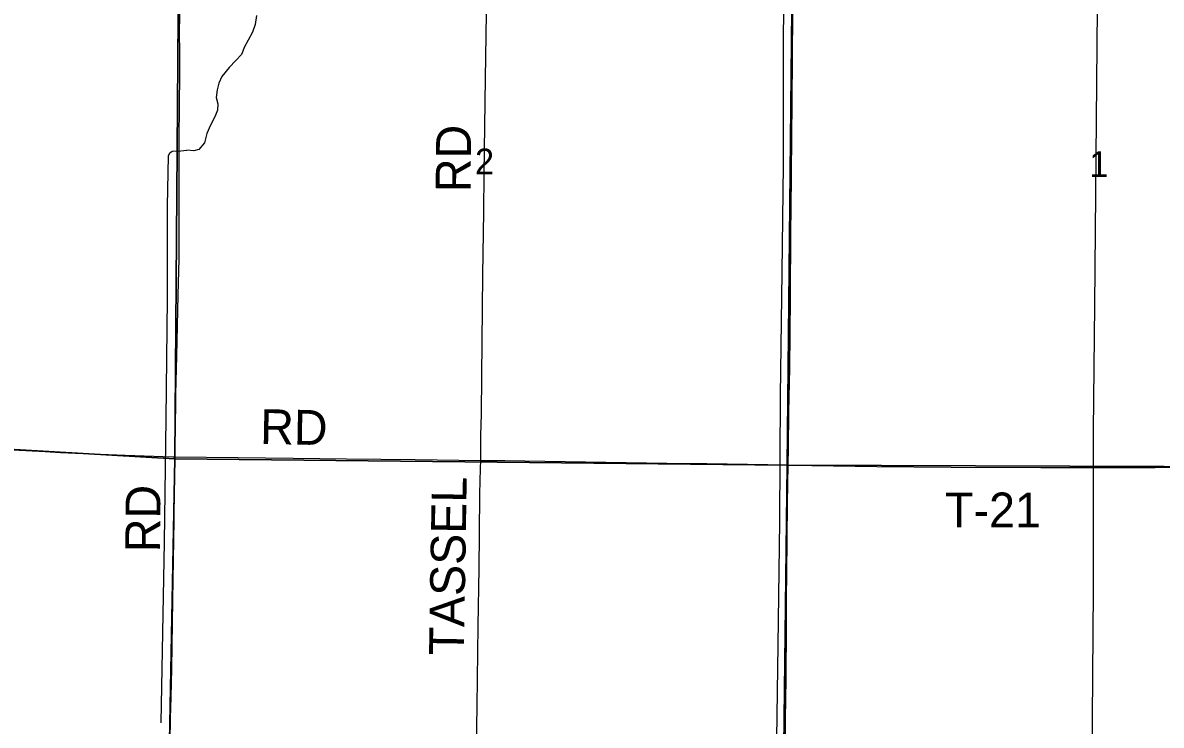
# Model space of a CAD drawing. Extents: x 1443599 to 1910620, y 1028088 to 1361369.
# Drawn here: x 1608527 to 1618321, y 1212815 to 1218862 of the extents above; entities that cross this region are included whole.
import ezdxf

# ---------------------------------------------------------------- set-up
doc = ezdxf.new("R2010")
doc.units = 0
for name, color, linetype in [('GM_X_Minor_River', 7, 'Continuous'), ('GM_X_Section', 7, 'Continuous'), ('GM_X_Section_Text', 7, 'Continuous'), ('GM_X_State_Route', 7, 'Continuous'), ('GM_X_Township_Road', 7, 'Continuous'), ('GM_X_Township_Road_Text', 7, 'Continuous')]:
    doc.layers.add(name, color=color, linetype=linetype)

msp = doc.modelspace()

# ---------------------------------------------------------------- linework, layer by layer
at = {"layer": 'GM_X_Minor_River'}
for points in [[(1617853.3, 1226327.9), (1617840.1, 1225049.4), (1617825.5, 1224051.8), (1617810.7, 1222799.8), (1617798, 1221193.2), (1617782.7, 1220157.6), (1617771.2, 1218983.8), (1617758, 1217707.9), (1617748.7, 1216428), (1617736.7, 1215352.4), (1617735.8, 1213978.3), (1617725.2, 1212506.2), (1617715, 1211422.7), (1617702.4, 1210197), (1617703.6, 1209429.7), (1617680.8, 1208428.5), (1617671.9, 1207420.9), (1617660.9, 1206527.6), (1617638.1, 1205167.5)], [(1615135.5, 1225234.5), (1615129.9, 1224405.5), (1615117.6, 1223546.2), (1615116.2, 1222376.2), (1615099.6, 1221134.4), (1615094.5, 1220467.4), (1615092.3, 1219854.4), (1615068.3, 1218777), (1615067.4, 1217637.2), (1615056, 1216713.9), (1615044.3, 1215650.5), (1615036.1, 1214564.9), (1615022.5, 1213507.5), (1615006.2, 1212293.8)], [(1610539, 1218924.3), (1610525.7, 1218846.4), (1610504.5, 1218780.7), (1610465.3, 1218711.3), (1610434.3, 1218653.7), (1610407.2, 1218590.1), (1610360.3, 1218536.9), (1610301.2, 1218475.8), (1610239.9, 1218400.8), (1610212.8, 1218341.2), (1610199.9, 1218285.3), (1610190.8, 1218219.4), (1610203.9, 1218163), (1610201, 1218111), (1610178, 1218053.3), (1610140.7, 1217979.8), (1610111.5, 1217910.2), (1610090.2, 1217828.5), (1610041.9, 1217772.2), (1609999.3, 1217760), (1609938.9, 1217765.1)], [(1609716.5, 1212835.8), (1609746.5, 1214392.3), (1609760.2, 1215456.1), (1609771.4, 1216485.8), (1609772.7, 1217283.2), (1609779.9, 1217715.9), (1609792.4, 1217743.7), (1609812.6, 1217757.3), (1609886.8, 1217760), (1609938.9, 1217765.1)]]:
    msp.add_lwpolyline(points, dxfattribs=at)
at = {"layer": 'GM_X_Section'}
for points in [[(1604565.2, 1220497.6), (1609830.1, 1220437.4), (1609876.1, 1220436.7), (1609835, 1215109.4), (1607170.3, 1215264), (1604507.5, 1215126.5)], [(1615157.1, 1220376.3), (1615104, 1215053), (1609835, 1215109.4), (1609876.1, 1220436.7)], [(1620446.9, 1220363.7), (1620417.2, 1215002), (1619967.5, 1215036.6), (1615104, 1215053), (1615157.1, 1220376.3)], [(1604507.5, 1215126.5), (1607170.3, 1215264), (1609835, 1215109.4), (1609736, 1209792.9), (1604408.8, 1209830.1)], [(1609835, 1215109.4), (1615104, 1215053), (1615038.9, 1209730), (1609736, 1209792.9)], [(1615104, 1215053), (1619967.5, 1215036.6), (1620417.2, 1215002), (1620382.4, 1209704.6), (1615038.9, 1209730)]]:
    msp.add_lwpolyline(points, close=True, dxfattribs=at)
at = {"layer": 'GM_X_State_Route'}
msp.add_lwpolyline([(1615085.8, 1212392.6), (1615089.7, 1212868.6), (1615093.7, 1213213.2), (1615097.7, 1213672.7), (1615098.4, 1213919), (1615101.7, 1214115.8), (1615107.4, 1214723.1), (1615112.1, 1215055.7), (1615114.1, 1215199), (1615118.6, 1215510.9), (1615125.8, 1215888.3), (1615131.6, 1216495.5), (1615135.6, 1217070), (1615138.4, 1217250.5), (1615145.6, 1218186), (1615151.6, 1218941), (1615152.7, 1219006.6)], dxfattribs=at)
at = {"layer": 'GM_X_Township_Road'}
for points in [[(1612468.4, 1215095.4), (1612468.5, 1215132.1), (1612469.1, 1215312.7), (1612473, 1215493.2), (1612475.9, 1215821.5), (1612486.2, 1216691.6), (1612493.2, 1217233.3), (1612496.8, 1217561.7), (1612507.9, 1218382.5), (1612516, 1218940.6), (1612518, 1219058.9)], [(1609835, 1215124.2), (1609835.9, 1215189.4), (1609841.3, 1215402.7), (1609844.6, 1215583.1), (1609844.4, 1215665.2), (1609853.2, 1215993.2), (1609856.3, 1216124.5), (1609864.1, 1216518.2), (1609871.7, 1216829.9), (1609872.2, 1216895.5), (1609871.2, 1216961.1), (1609873.3, 1217043.1), (1609872.6, 1217108.8), (1609873, 1217240.1), (1609872.5, 1217519), (1609873.1, 1217617.4), (1609872.4, 1217715.9), (1609871.3, 1217781.5), (1609872.1, 1217847.2), (1609874.8, 1218158.9), (1609876.9, 1218407.3), (1609878.6, 1218618.4), (1609874.2, 1218765.9), (1609877.8, 1218937.3)], [(1607200.5, 1215257.7), (1607261.2, 1215256), (1607457.9, 1215244.8), (1607801.9, 1215222.2), (1608162.4, 1215201.9), (1608440.9, 1215185.8), (1608719.5, 1215171.1), (1608850.6, 1215164.1), (1608981.6, 1215158.3), (1609408, 1215141.1), (1609817.9, 1215124.4), (1609835, 1215124.2)], [(1609749.8, 1209795.4), (1609753.4, 1210037.6), (1609758.8, 1210267.3), (1609762.8, 1210513.4), (1609766.1, 1210693.9), (1609770.5, 1211022), (1609775.1, 1211333.8), (1609776.9, 1211448.6), (1609781.4, 1211678.3), (1609789.8, 1212383.8), (1609791.7, 1212482.3), (1609794.8, 1212679.1), (1609799.1, 1212876), (1609803.2, 1213056.4), (1609808, 1213302.5), (1609817.6, 1213893.2), (1609828, 1214582.3), (1609835, 1215124.2)], [(1609835, 1215124.2), (1610375.8, 1215118.6), (1610851.9, 1215113), (1611311.3, 1215107.2), (1611902.2, 1215102.2), (1612468.4, 1215095.4)], [(1612437.1, 1209776.3), (1612436.5, 1209827.4), (1612435.1, 1209975.3), (1612440, 1210583.3), (1612445.7, 1211224.2), (1612451.8, 1211733.6), (1612456.3, 1211897.9), (1612455.5, 1212045.7), (1612453.9, 1212259.4), (1612450.7, 1212341.4), (1612441.3, 1212489), (1612435.9, 1212636.8), (1612433.7, 1212801.2), (1612435, 1212981.9), (1612440.6, 1213442), (1612444.3, 1213672), (1612452.4, 1214165), (1612456.2, 1214460.8), (1612460.2, 1214805.8), (1612466, 1215025.5), (1612468.4, 1215095.4)], [(1612468.4, 1215095.4), (1612673.6, 1215093), (1613018.2, 1215087.9), (1613543.5, 1215080.7), (1614068.6, 1215071.9), (1614413.3, 1215067.4), (1615112.1, 1215055.7)], [(1615112.1, 1215055.7), (1615250.2, 1215053.4), (1615315.9, 1215051.3), (1615873.8, 1215042.3), (1616513.9, 1215036.2), (1617285.3, 1215032.8), (1617958.3, 1215032.4), (1618270.1, 1215034.4), (1618696.9, 1215035.6), (1618975.9, 1215034.6), (1619189.3, 1215035.4), (1619533.9, 1215036.4), (1619911.5, 1215038.3), (1620042.9, 1215036.4), (1620125, 1215032.8), (1620239.6, 1215022.4), (1620434.9, 1215000.3)]]:
    msp.add_lwpolyline(points, dxfattribs=at)

# ---------------------------------------------------------------- texts
at = {"layer": 'GM_X_Section_Text'}
for s, p in [('2', (1612417.7, 1217557.7)), ('1', (1617702.1, 1217534.1))]:
    msp.add_text(s, height=221, rotation=0.00001, dxfattribs=at).set_placement(p)
at = {"layer": 'GM_X_Township_Road_Text'}
for s, rotation, p in [('RD', 89.50633, (1612379, 1217402.8)), ('RD', 359.01279, (1610567.3, 1215236.1)), ('TASSEL', 89.06595, (1612321.7, 1213414.1)), ('RD', 89.50619, (1609708.2, 1214303.5)), ('T-21', 0.00001, (1616461.3, 1214518.2))]:
    msp.add_text(s, height=300, rotation=rotation, dxfattribs=at).set_placement(p)

doc.saveas('drawing.dxf')
